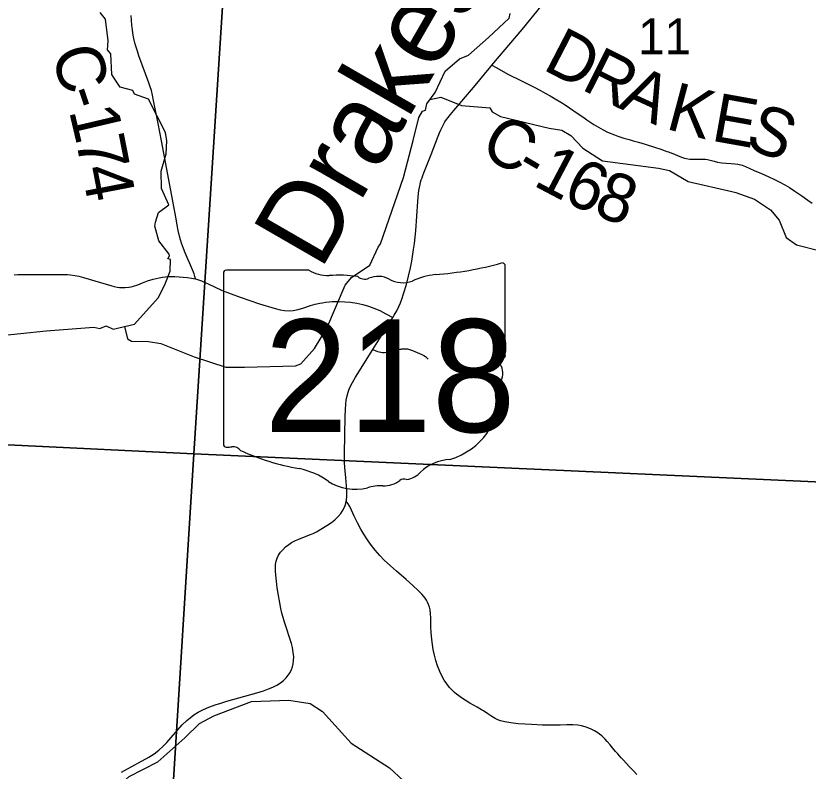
# Model space of a CAD drawing. Extents: x -2.1 to 31.9, y 6.3 to 28.3.
# Drawn here: x 3.259 to 4.186, y 23.525 to 24.409 of the extents above; entities that cross this region are included whole.
import ezdxf

# ---------------------------------------------------------------- set-up
doc = ezdxf.new("R2010")
doc.units = 0
for name, color, linetype in [('GM_X_County_Road', 7, 'Continuous'), ('GM_X_County_Road_Text', 7, 'Continuous'), ('GM_X_Minor_River', 7, 'Continuous'), ('GM_X_Minor_River_Text', 7, 'Continuous'), ('GM_X_Section', 7, 'Continuous'), ('GM_X_Section_Text', 7, 'Continuous'), ('GM_X_State_Location', 7, 'Continuous'), ('GM_X_State_Route', 7, 'Continuous'), ('GM_X_State_Shield', 7, 'Continuous'), ('GM_X_Township_Road', 7, 'Continuous')]:
    doc.layers.add(name, color=color, linetype=linetype)

msp = doc.modelspace()

# ---------------------------------------------------------------- linework, layer by layer
at = {"layer": 'GM_X_County_Road'}
for points in [[(3.46921, 24.10113), (3.46852, 24.104), (3.46769, 24.10684), (3.46685, 24.10909), (3.46568, 24.11185), (3.45718, 24.13136), (3.4551, 24.13663), (3.45296, 24.14289), (3.45176, 24.1468), (3.45054, 24.15118), (3.44899, 24.15779), (3.44788, 24.16385), (3.44657, 24.17122), (3.44134, 24.19809), (3.42961, 24.26266), (3.42554, 24.28283), (3.42004, 24.30992), (3.41888, 24.31592), (3.41754, 24.32159), (3.41627, 24.32578), (3.41479, 24.33053), (3.40307, 24.36212), (3.40118, 24.36746), (3.3994, 24.37313), (3.39832, 24.377), (3.39751, 24.38036), (3.39666, 24.38434), (3.39595, 24.38837), (3.39532, 24.39296), (3.39475, 24.3974), (3.39414, 24.40354), (3.39377, 24.40931)], [(3.81606, 24.35089), (3.82167, 24.34784), (3.8349, 24.34063), (3.84981, 24.33299), (3.86488, 24.32559), (3.87315, 24.32141), (3.87853, 24.31845), (3.88436, 24.31513), (3.89005, 24.31172), (3.89666, 24.30764), (3.90164, 24.30454), (3.90698, 24.30111), (3.91606, 24.29501), (3.92383, 24.28966), (3.92724, 24.2873), (3.93556, 24.28153), (3.94065, 24.2784), (3.94647, 24.27524), (3.9514, 24.27284), (3.95939, 24.26946), (3.96346, 24.26795), (3.97057, 24.2657), (3.97654, 24.26401), (3.98131, 24.26271), (3.98783, 24.26102), (3.99543, 24.25883), (4.00633, 24.2552), (4.01369, 24.25266), (4.01875, 24.2509), (4.02098, 24.25007), (4.02269, 24.24958), (4.02433, 24.24888), (4.02603, 24.24837), (4.03814, 24.24344), (4.04159, 24.24238), (4.04333, 24.24194), (4.04754, 24.24129), (4.05182, 24.24107), (4.06169, 24.24114), (4.06602, 24.24098), (4.06847, 24.24066), (4.07148, 24.23985), (4.07632, 24.23876), (4.07998, 24.23774), (4.08528, 24.23693), (4.09038, 24.23631), (4.09598, 24.23596), (4.10031, 24.23557), (4.104, 24.23514), (4.10879, 24.23391), (4.11288, 24.23247), (4.1231, 24.228), (4.13165, 24.22434), (4.14016, 24.22055), (4.14689, 24.21735), (4.15296, 24.21423), (4.15901, 24.21109), (4.16437, 24.20798), (4.17056, 24.20386), (4.17864, 24.19809), (4.18586, 24.19323), (4.19079, 24.18956)], [(3.25705, 24.10587), (3.26113, 24.10604), (3.31051, 24.10629), (3.31527, 24.10621), (3.31927, 24.10604), (3.32286, 24.10579), (3.32794, 24.10504), (3.33278, 24.10412), (3.33812, 24.10279), (3.37123, 24.09284), (3.37416, 24.09211), (3.37749, 24.0915), (3.38041, 24.09111), (3.38366, 24.09086), (3.38708, 24.09094), (3.39117, 24.09137), (3.39401, 24.09186), (3.39684, 24.09258), (3.40163, 24.0942), (3.40701, 24.09639), (3.41302, 24.09864), (3.41968, 24.10073), (3.42653, 24.10246), (3.43078, 24.10321), (3.4341, 24.10358), (3.43735, 24.10377), (3.4406, 24.10383), (3.44511, 24.10371), (3.44993, 24.10346), (3.45483, 24.10311), (3.45946, 24.10261), (3.46459, 24.10198), (3.46921, 24.10113), (3.47285, 24.0999), (3.47628, 24.09865), (3.47928, 24.09732), (3.48314, 24.09558), (3.50052, 24.0876), (3.52165, 24.07959), (3.54409, 24.072), (3.5623, 24.06655), (3.56847, 24.06496), (3.57356, 24.06405), (3.57882, 24.06371), (3.58365, 24.06396), (3.58932, 24.06513), (3.59594, 24.0672), (3.60394, 24.06988), (3.60939, 24.07145), (3.61471, 24.07264), (3.61796, 24.0732), (3.62121, 24.07371), (3.62572, 24.0742), (3.62928, 24.07451), (3.63316, 24.07464), (3.63716, 24.07458), (3.64393, 24.07443), (3.65068, 24.07383), (3.65798, 24.07269), (3.66521, 24.07111), (3.67172, 24.06925), (3.67807, 24.06693), (3.68485, 24.06398), (3.69197, 24.0603), (3.70021, 24.05605)], [(3.98563, 23.52149), (3.98167, 23.52565), (3.97689, 23.53067), (3.96991, 23.538), (3.96725, 23.54096), (3.96331, 23.54535), (3.96069, 23.54833), (3.95727, 23.55236), (3.95433, 23.55595), (3.951, 23.56003), (3.94848, 23.56278), (3.94459, 23.56651), (3.94192, 23.56867), (3.94001, 23.57), (3.93627, 23.57245), (3.93472, 23.57336), (3.93238, 23.5744), (3.92967, 23.57549), (3.92507, 23.57716), (3.92094, 23.57823), (3.91674, 23.57898), (3.91065, 23.57949), (3.90392, 23.57941), (3.89596, 23.57903), (3.89236, 23.57888), (3.88862, 23.57898), (3.88432, 23.5789), (3.87516, 23.57919), (3.86232, 23.57975), (3.84699, 23.58079), (3.83842, 23.58176), (3.83104, 23.58297), (3.82616, 23.58426), (3.82317, 23.58535), (3.81973, 23.58697), (3.81594, 23.5892), (3.81136, 23.59241), (3.80617, 23.59575), (3.80404, 23.59695), (3.79871, 23.59999), (3.79021, 23.60497), (3.78492, 23.60823), (3.78057, 23.6112), (3.77721, 23.6135), (3.77456, 23.6155), (3.77234, 23.61745), (3.76957, 23.62001), (3.7666, 23.62329), (3.76347, 23.62723), (3.76027, 23.63189), (3.75721, 23.63737), (3.75505, 23.6419), (3.75248, 23.6483), (3.75033, 23.65485), (3.74883, 23.66092), (3.74749, 23.66767), (3.74664, 23.67323), (3.74591, 23.67941), (3.74518, 23.6875), (3.74478, 23.69372), (3.74455, 23.69995), (3.74444, 23.70428), (3.74417, 23.70978), (3.74368, 23.71378), (3.74299, 23.71695), (3.74182, 23.72034), (3.74079, 23.72289), (3.73941, 23.72538), (3.73802, 23.72759), (3.73637, 23.72973), (3.73409, 23.73221), (3.73029, 23.73601), (3.72338, 23.74243), (3.71565, 23.74941), (3.7044, 23.75935), (3.69735, 23.76536), (3.68987, 23.77191), (3.68479, 23.77737), (3.6794, 23.78372), (3.67416, 23.79083), (3.66967, 23.79712), (3.66629, 23.8023), (3.66256, 23.80844), (3.65876, 23.81555), (3.65489, 23.82356), (3.65172, 23.83074), (3.64978, 23.83468), (3.64792, 23.83786), (3.64571, 23.84106)]]:
    msp.add_lwpolyline(points, dxfattribs=at)
at = {"layer": 'GM_X_Minor_River'}
for points in [[(3.23409, 24.03397), (3.29457, 24.0402), (3.35013, 24.04451), (3.35732, 24.043), (3.3645, 24.04606), (3.37282, 24.04228), (3.39776, 24.04804), (3.42571, 24.07889), (3.43287, 24.09334), (3.43966, 24.11008), (3.44003, 24.12376), (3.43701, 24.12452), (3.43889, 24.12794), (3.43851, 24.12984), (3.4264, 24.14578), (3.42147, 24.16287), (3.4226, 24.16743), (3.42599, 24.17884), (3.43808, 24.18761), (3.42937, 24.20697), (3.42897, 24.22711), (3.435, 24.24727), (3.43574, 24.26247), (3.43422, 24.27235), (3.41415, 24.31145), (3.39789, 24.31711), (3.396, 24.32129), (3.38125, 24.32543), (3.3733, 24.3372), (3.37141, 24.34023), (3.37025, 24.36418), (3.36609, 24.36911), (3.36684, 24.37937), (3.36379, 24.40482), (3.35773, 24.41279)], [(3.38624, 24.04538), (3.38984, 24.03092), (3.39437, 24.02826), (3.41403, 24.02793), (3.42878, 24.02569), (3.46773, 24.00981), (3.50479, 23.99774), (3.52671, 23.99779), (3.58606, 23.99945), (3.59248, 24.00174), (3.60834, 24.01964), (3.62307, 24.04324), (3.64419, 24.09383), (3.65174, 24.10259), (3.67328, 24.11708), (3.68309, 24.13801), (3.68573, 24.14219), (3.7125, 24.21979), (3.7238, 24.26276), (3.73058, 24.28976), (3.73473, 24.29737), (3.73851, 24.29852), (3.74001, 24.30574), (3.74983, 24.31907), (3.76153, 24.34418), (3.77815, 24.35866), (3.78873, 24.36286), (3.81215, 24.38344), (3.83632, 24.40592), (3.83745, 24.41162)], [(3.74331, 24.31087), (3.75641, 24.31372), (3.78067, 24.30383), (3.81386, 24.30125), (3.81637, 24.29662), (3.82602, 24.29099), (3.88294, 24.27742)], [(3.88294, 24.27742), (3.89811, 24.27502), (3.9085, 24.26861), (3.92243, 24.25412), (3.94541, 24.23934), (4.01091, 24.23041), (4.02406, 24.22771), (4.04559, 24.21487), (4.09703, 24.20336), (4.10153, 24.20207), (4.12321, 24.19417), (4.14211, 24.18179), (4.15233, 24.16969), (4.16041, 24.14931), (4.17263, 24.14095), (4.20039, 24.13399)], [(3.29831, 23.41945), (3.30194, 23.42533), (3.36454, 23.4951), (3.39172, 23.51891), (3.42512, 23.53607), (3.4566, 23.56429), (3.47373, 23.58083), (3.49065, 23.59017), (3.53462, 23.60661), (3.57851, 23.60824), (3.60334, 23.60441), (3.6178, 23.59522), (3.65145, 23.55807), (3.69632, 23.5293), (3.7294, 23.49825), (3.76386, 23.42576), (3.77378, 23.41633), (3.7812, 23.41192), (3.80317, 23.40096), (3.80892, 23.39091), (3.82291, 23.37869), (3.86786, 23.35246)]]:
    msp.add_lwpolyline(points, dxfattribs=at)
at = {"layer": 'GM_X_Section'}
for points in [[(2.47863, 24.97086), (3.53282, 24.91852), (3.46714, 23.89651), (2.4194, 23.94697)], [(3.53282, 24.91852), (4.5692, 24.86614), (4.50616, 23.84982), (3.46714, 23.89651)], [(2.4194, 23.94697), (3.46714, 23.89651), (3.4412, 23.47766), (3.41605, 23.05625), (3.4084, 22.89794), (2.80851, 22.92636), (2.36122, 22.95264), (2.36141, 22.95619), (2.37093, 23.13483), (2.39381, 23.54828)], [(3.46714, 23.89651), (4.50616, 23.84982), (4.47911, 23.42948), (3.4412, 23.47766)]]:
    msp.add_lwpolyline(points, close=True, dxfattribs=at)
at = {"layer": 'GM_X_State_Route'}
msp.add_lwpolyline([(3.38251, 23.5242), (3.38606, 23.52607), (3.41446, 23.54147), (3.42075, 23.54557), (3.4262, 23.54981), (3.43127, 23.55446), (3.4356, 23.55898), (3.45378, 23.57939), (3.45905, 23.58456), (3.46279, 23.58774), (3.46722, 23.59103), (3.47243, 23.59426), (3.47846, 23.5973), (3.48469, 23.59999), (3.49222, 23.60277), (3.49875, 23.60489), (3.50583, 23.607), (3.54114, 23.61679), (3.54898, 23.6193), (3.55461, 23.62138), (3.55991, 23.62365), (3.56453, 23.626), (3.56871, 23.62863), (3.57212, 23.63148), (3.57527, 23.63461), (3.57769, 23.63757), (3.57982, 23.64075), (3.58155, 23.64418), (3.58266, 23.64718), (3.58359, 23.65089), (3.58407, 23.65468), (3.58411, 23.65913), (3.58366, 23.66416), (3.58267, 23.66973), (3.58144, 23.6746), (3.57343, 23.69937), (3.57163, 23.70515), (3.5704, 23.71008), (3.56916, 23.71547), (3.56487, 23.73976), (3.56395, 23.74732), (3.56319, 23.75446), (3.56285, 23.75942), (3.56275, 23.76356), (3.563, 23.76702), (3.56376, 23.77081), (3.56483, 23.77434), (3.56653, 23.77799), (3.5688, 23.78133), (3.57126, 23.78429), (3.5746, 23.78757), (3.57844, 23.79047), (3.58174, 23.79261), (3.58607, 23.79488), (3.59014, 23.79664), (3.60265, 23.80155), (3.60676, 23.80315), (3.61084, 23.80521), (3.62309, 23.81262), (3.62819, 23.81627), (3.63211, 23.81942), (3.63599, 23.82297), (3.63921, 23.82662), (3.64129, 23.82965), (3.64325, 23.83318), (3.64438, 23.83601), (3.64526, 23.83885), (3.64571, 23.84106), (3.64596, 23.84232), (3.6464, 23.84635), (3.64646, 23.85063), (3.64627, 23.8544), (3.64506, 23.86839), (3.64402, 23.88045), (3.64372, 23.88623), (3.64356, 23.89136), (3.64358, 23.89673), (3.64449, 23.9402), (3.64475, 23.94829), (3.6452, 23.95456), (3.64571, 23.95935), (3.64663, 23.96413), (3.64781, 23.96842), (3.64915, 23.9722), (3.65058, 23.97573), (3.65277, 23.97993), (3.65643, 23.98594), (3.67668, 24.01835), (3.68253, 24.02771), (3.70021, 24.05605), (3.70185, 24.05869), (3.70467, 24.06378), (3.70726, 24.06894), (3.70909, 24.07317), (3.71073, 24.07732), (3.71274, 24.08344), (3.71602, 24.09463), (3.72071, 24.11398), (3.72228, 24.12199), (3.72442, 24.13558), (3.72534, 24.14229), (3.72619, 24.14969), (3.72695, 24.15714), (3.72957, 24.19173), (3.72993, 24.19654), (3.73031, 24.20083), (3.73068, 24.20429), (3.73131, 24.20813), (3.732, 24.21148), (3.7327, 24.21425), (3.73344, 24.2168), (3.73432, 24.21944), (3.73517, 24.22185), (3.73639, 24.22512), (3.74483, 24.24665), (3.75315, 24.2679), (3.75492, 24.27205), (3.75643, 24.27552), (3.75782, 24.27848), (3.75946, 24.28163), (3.76109, 24.28459), (3.76292, 24.28743), (3.76489, 24.29), (3.76763, 24.2934), (3.76948, 24.29556), (3.77143, 24.29785), (3.79448, 24.32511), (3.81487, 24.34948), (3.81606, 24.35089), (3.85131, 24.39297), (3.87393, 24.41996)], dxfattribs=at)
at = {"layer": 'GM_X_State_Shield'}
for p, q in [((3.50208, 24.10791), (3.50208, 23.90779)), ((3.60185, 24.11136), (3.50533, 24.11136)), ((3.83167, 24.01163), (3.83167, 24.11632)), ((3.83163, 24.01166), (3.83167, 24.01163))]:
    msp.add_line(p, q, dxfattribs=at)
for centre, major_axis, start_param, end_param in [((3.71426, 24.38419), (0.34952, 0), 4.814394, 5.042369), ((3.82801, 24.11675), (0.00367, 0), 6.141152, 7.989035), ((3.50586, 24.10834), (0.00382, 0), 1.712693, 3.28349), ((3.62483, 24.13459), (0.03703, 0), 4.042523, 4.731795), ((3.63711, 23.99901), (0.13295, 0), 1.404758, 1.657858), ((3.6673, 24.10938), (0.01068, 0), 3.836095, 5.185415), ((3.68298, 24.08625), (0.02221, 0), 0.950623, 2.079405), ((3.71165, 24.11797), (0.02672, 0), 4.081561, 5.145723), ((3.75885, 24.05024), (0.07032, 0), 1.699011, 2.107814), ((3.83082, 24.00395), (0.00568, 0), 1.883978, 3.671073), ((3.82775, 24.01123), (0.00393, 0), 5.05454, 6.418171), ((3.79469, 23.99071), (0.03409, 0), 5.934695, 6.695948), ((3.84481, 23.96782), (0.0248, 0), 2.387724, 3.262537), ((3.73384, 23.95451), (0.08742, 0), 5.101752, 6.440018), ((3.50589, 23.90736), (0.00385, 0), 3.00124, 4.508301), ((3.50648, 23.92783), (0.0294, 0), 4.665946, 4.897461), ((3.51249, 23.89625), (0.0106, 0), 0.519207, 1.627899), ((3.64632, 24.07605), (0.2524, 0), 4.195997, 4.488961), ((3.7707, 23.85161), (0.04788, 0), 1.647645, 2.488434), ((3.57107, 23.81789), (0.07897, 0), 0.823519, 1.323587), ((3.71325, 23.86089), (0.00752, 0), 1.147584, 2.315152), ((3.71004, 23.8884), (0.02824, 0), 4.937069, 5.64225), ((3.65648, 23.89526), (0.05011, 0), 4.026481, 4.996735), ((3.68543, 23.82607), (0.04118, 0), 1.495662, 1.94098), ((3.68909, 23.88027), (0.0267, 0), 4.691044, 5.507374)]:
    msp.add_ellipse(centre, major_axis=major_axis, ratio=0.8, start_param=start_param, end_param=end_param, dxfattribs=at)
at = {"layer": 'GM_X_Township_Road'}
msp.add_lwpolyline([(3.67668, 24.01835), (3.67965, 24.01729), (3.68238, 24.01632), (3.68411, 24.01575), (3.68599, 24.01538), (3.68822, 24.01516), (3.6904, 24.0151), (3.69275, 24.01519), (3.69538, 24.01547), (3.69763, 24.01585), (3.69955, 24.01627), (3.70134, 24.01674), (3.70855, 24.01873), (3.70971, 24.01897), (3.71086, 24.01914), (3.71216, 24.0193), (3.71343, 24.01935), (3.7147, 24.01933), (3.71596, 24.01926), (3.71716, 24.01912), (3.71843, 24.01888), (3.71966, 24.01859), (3.72078, 24.01824), (3.72191, 24.01782), (3.72319, 24.01729), (3.73423, 24.01251), (3.73636, 24.01139), (3.73824, 24.01021), (3.74001, 24.00879), (3.74166, 24.00726)], dxfattribs=at)

# ---------------------------------------------------------------- texts
at = {"layer": 'GM_X_County_Road_Text'}
for s, rotation, p in [('D', 332.64483, (3.87409, 24.34674)), ('C', 285.97436, (3.30014, 24.36638)), ('R', 333.30205, (3.91913, 24.32344)), ('A', 335.21028, (3.96268, 24.30158)), ('K', 345.07952, (4.01812, 24.27699)), ('-', 288.67645, (3.31385, 24.31873)), ('E', 349.86389, (4.07148, 24.26299)), ('S', 337.73359, (4.11027, 24.2564)), ('1', 283.24172, (3.32094, 24.29799)), ('C', 328.62594, (3.79963, 24.24919)), ('7', 281.13899, (3.32884, 24.26446)), ('1', 332.15829, (3.86293, 24.21121)), ('-', 329.6337, (3.84041, 24.22434)), ('6', 335.17452, (3.89681, 24.19342)), ('4', 280.916, (3.33559, 24.23018)), ('8', 339.49813, (3.93289, 24.17692))]:
    msp.add_text(s, height=0.05682, rotation=rotation, dxfattribs=at).set_placement(p)
at = {"layer": 'GM_X_Minor_River_Text'}
msp.add_text('Drakes', height=0.094689, rotation=59.99477, dxfattribs=at).set_placement((3.61533, 24.10973))
at = {"layer": 'GM_X_Section_Text'}
msp.add_text('11', height=0.041856, rotation=0.00001, dxfattribs=at).set_placement((3.98701, 24.36387))
at = {"layer": 'GM_X_State_Location'}
for s, p in [('s', (3.57637, 23.59495)), ('r', (3.57636, 23.59495))]:
    msp.add_text(s, height=0.000189, dxfattribs=at).set_placement(p)
msp.add_text('218', height=0.000189, rotation=0.00001, dxfattribs=at).set_placement((3.50951, 23.58117))
at = {"layer": 'GM_X_State_Shield'}
msp.add_text('218', height=0.131836, dxfattribs=at).set_placement((3.5497, 23.92191))

doc.saveas('drawing.dxf')
